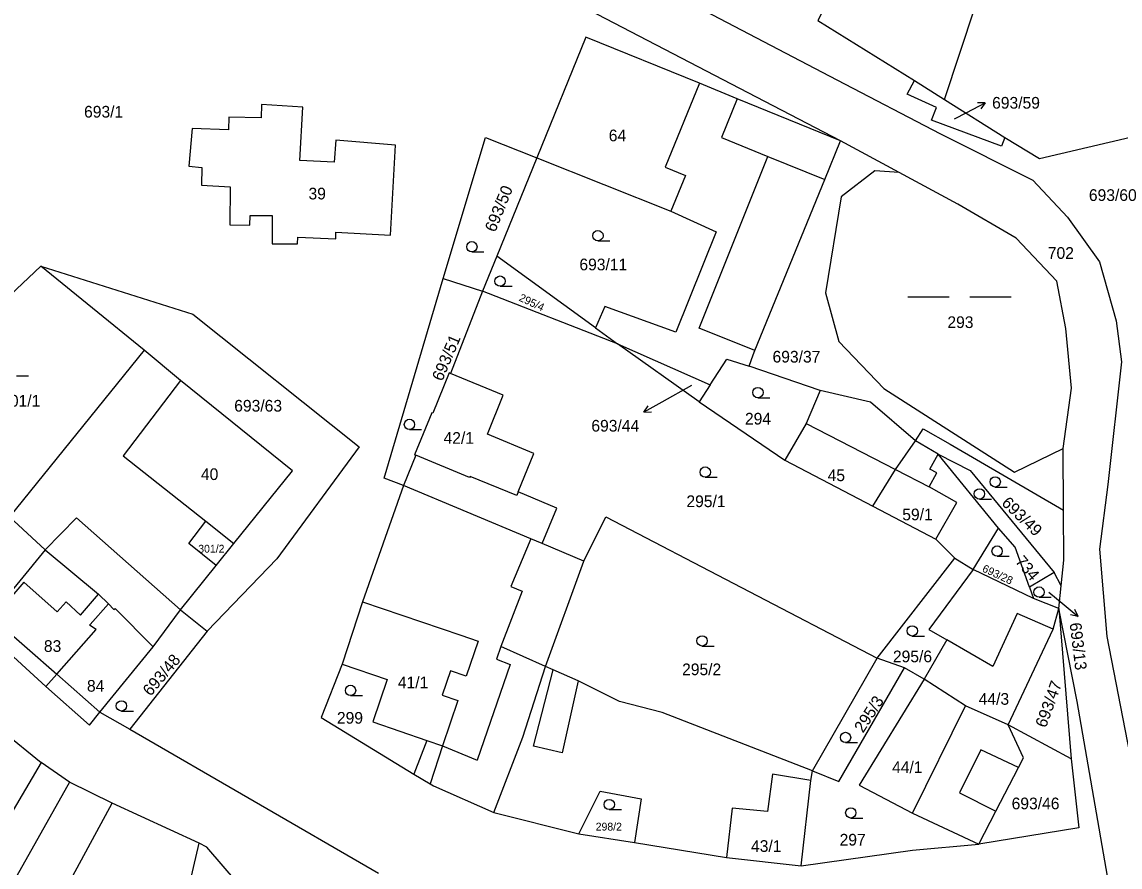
# Model space of a CAD drawing. Extents: x -7483133 to -743169, y -11317770 to -1127091.
# Drawn here: x -746401 to -746241.3, y -1132211.8 to -1132088.9 of the extents above; entities that cross this region are included whole.
import ezdxf

# ---------------------------------------------------------------- set-up
doc = ezdxf.new("R2010")
doc.units = 0
for name, color, linetype in [('Hranice parcel', 7, 'Continuous'), ('Parcelní čísla', 7, 'Continuous'), ('Pop  PČ popisy', 7, 'Continuous'), ('Vnitřní kresba', 7, 'Continuous'), ('Značky kultur', 7, 'Continuous')]:
    doc.layers.add(name, color=color, linetype=linetype)

msp = doc.modelspace()

# ---------------------------------------------------------------- linework, layer by layer
at = {"layer": 'Hranice parcel'}
for p, q in [((-746271.22, -1132097.41), (-746266.88, -1132100.2)), ((-746266.88, -1132100.2), (-746258.07, -1132105.71)), ((-746273.47, -1132110.79), (-746281.98, -1132106.18)), ((-746326.13, -1132108.66), (-746331.96, -1132122.97)), ((-746326.13, -1132108.66), (-746306.63, -1132116.44)), ((-746331.96, -1132122.97), (-746334.03, -1132128.06)), ((-746317.6, -1132133.4), (-746331.96, -1132122.97)), ((-746398.24, -1132124.43), (-746402.67, -1132128.64)), ((-746383.2, -1132136.66), (-746398.24, -1132124.43)), ((-746398.24, -1132124.43), (-746376.13, -1132131.39)), ((-746339.72, -1132126.2), (-746334.03, -1132128.06)), ((-746334.03, -1132128.06), (-746338.7, -1132140.02)), ((-746314.39, -1132135.73), (-746334.03, -1132128.06)), ((-746317.6, -1132133.4), (-746314.39, -1132135.73)), ((-746314.39, -1132135.73), (-746300.91, -1132141.67)), ((-746302.53, -1132144.17), (-746314.39, -1132135.73)), ((-746383.2, -1132136.66), (-746402.78, -1132160.86)), ((-746284.93, -1132142.52), (-746295.24, -1132138.98)), ((-746338.7, -1132140.02), (-746338.87, -1132139.95)), ((-746331.03, -1132143.2), (-746338.7, -1132140.02)), ((-746300.91, -1132141.67), (-746302.53, -1132144.17)), ((-746302.53, -1132144.17), (-746290.06, -1132152.64)), ((-746271.08, -1132149.84), (-746269.98, -1132148.07)), ((-746267.76, -1132151.76), (-746271.08, -1132149.84)), ((-746259.02, -1132162.52), (-746267.76, -1132151.76)), ((-746249.58, -1132159.89), (-746249.63, -1132150.94)), ((-746290.06, -1132152.64), (-746277.28, -1132159.31)), ((-746370.18, -1132164.75), (-746361.64, -1132154.17)), ((-746327.01, -1132164.06), (-746345.51, -1132156.33)), ((-746402.78, -1132160.86), (-746397.61, -1132165.68)), ((-746249.5, -1132167.15), (-746249.58, -1132159.89)), ((-746262.67, -1132168.54), (-746259.02, -1132162.52)), ((-746325.35, -1132164.75), (-746327.01, -1132164.06)), ((-746397.61, -1132165.68), (-746406.86, -1132176.98)), ((-746397.61, -1132165.68), (-746389.84, -1132172.12)), ((-746372.76, -1132167.96), (-746370.18, -1132164.75)), ((-746319.28, -1132167.34), (-746325.35, -1132164.75)), ((-746324.85, -1132182.62), (-746319.28, -1132167.34)), ((-746276.66, -1132181.4), (-746265.37, -1132166.88)), ((-746265.37, -1132166.88), (-746262.67, -1132168.54)), ((-746249.91, -1132170.92), (-746249.5, -1132167.15)), ((-746377.93, -1132174.38), (-746372.76, -1132167.96)), ((-746262.67, -1132168.54), (-746269.15, -1132177.26)), ((-746253.91, -1132172.73), (-746262.67, -1132168.54)), ((-746250.91, -1132168.99), (-746254.52, -1132171.09)), ((-746249.91, -1132170.92), (-746250.91, -1132168.99)), ((-746250.26, -1132174.19), (-746249.91, -1132170.92)), ((-746389.84, -1132172.12), (-746388.41, -1132173.53)), ((-746254.52, -1132171.09), (-746253.91, -1132172.73)), ((-746250.26, -1132174.19), (-746253.91, -1132172.73)), ((-746381.9, -1132179.76), (-746377.93, -1132174.38)), ((-746377.93, -1132174.38), (-746374.04, -1132177.52)), ((-746251.07, -1132177.2), (-746250.26, -1132174.19)), ((-746250.26, -1132174.19), (-746248.47, -1132196.06)), ((-746406.86, -1132176.98), (-746397.51, -1132185.52)), ((-746257.62, -1132191.11), (-746251.07, -1132177.2)), ((-746374.04, -1132177.52), (-746385.31, -1132191.74)), ((-746389.67, -1132189.29), (-746381.9, -1132179.76)), ((-746286.03, -1132197.8), (-746276.66, -1132181.4)), ((-746272.66, -1132182.81), (-746276.66, -1132181.4)), ((-746269.83, -1132184.49), (-746272.66, -1132182.81)), ((-746397.51, -1132185.52), (-746395.9, -1132183.77)), ((-746389.67, -1132189.29), (-746385.31, -1132191.74)), ((-746248.47, -1132196.06), (-746257.62, -1132191.11)), ((-746403.66, -1132192.14), (-746398.19, -1132196.61)), ((-746385.31, -1132191.74), (-746349.14, -1132212.69)), ((-746342.14, -1132193.39), (-746344.02, -1132198.28)), ((-746398.19, -1132196.61), (-746414.98, -1132225.06)), ((-746394.06, -1132199.47), (-746398.19, -1132196.61)), ((-746394.06, -1132199.47), (-746409.61, -1132226.97)), ((-746387.86, -1132202.51), (-746394.06, -1132199.47)), ((-746341.17, -1132199.97), (-746332.36, -1132203.87)), ((-746402.53, -1132229.49), (-746387.86, -1132202.51)), ((-746375.2, -1132208.32), (-746387.86, -1132202.51)), ((-746332.36, -1132203.87), (-746320.04, -1132206.95)), ((-746320.04, -1132206.95), (-746311.91, -1132208.23))]:
    msp.add_line(p, q, dxfattribs=at)
for points in [[(-746266.88, -1132100.2), (-746262.42, -1132086.72), (-746242.88, -1132045.31)], [(-746281.98, -1132106.18), (-746317.29, -1132087.85), (-746364.32, -1132063.67)], [(-746324.12, -1132075.54), (-746282.49, -1132097.32), (-746267.43, -1132105.17), (-746254.03, -1132111.91), (-746248.97, -1132117.3)], [(-746282.45, -1132083.18), (-746285.29, -1132088.71), (-746271.22, -1132097.41)], [(-746258.07, -1132105.71), (-746253.04, -1132108.76), (-746235.88, -1132104.76), (-746228.31, -1132088.24)], [(-746281.98, -1132106.18), (-746296.99, -1132100.07), (-746302.49, -1132097.83), (-746318.98, -1132091.11), (-746326.13, -1132108.66)], [(-746258.07, -1132105.71), (-746258.56, -1132106.96), (-746268.77, -1132103.18), (-746268.04, -1132101.35), (-746272.31, -1132099.42), (-746271.22, -1132097.41)], [(-746355.36, -1132120.45), (-746355.33, -1132119.49), (-746347.42, -1132119.91), (-746346.68, -1132106.82), (-746355.36, -1132106.11), (-746355.58, -1132109.28), (-746360.59, -1132109.08), (-746360.16, -1132101.31), (-746366.14, -1132100.93), (-746366.2, -1132102.85), (-746370.91, -1132102.78), (-746370.97, -1132104.58), (-746376.22, -1132104.42), (-746376.7, -1132109.89), (-746374.83, -1132110.1), (-746374.9, -1132112.66), (-746370.69, -1132112.9), (-746370.75, -1132118.4), (-746367.87, -1132118.47), (-746367.81, -1132117.06), (-746364.58, -1132117.06), (-746364.61, -1132121.16), (-746360.9, -1132121.16), (-746360.86, -1132120.23), (-746355.36, -1132120.45)], [(-746339.72, -1132126.2), (-746333.57, -1132105.7), (-746326.13, -1132108.66)], [(-746295.24, -1132138.98), (-746294.66, -1132137.31), (-746294.42, -1132136.7), (-746284.28, -1132111.82), (-746281.98, -1132106.18)], [(-746273.47, -1132110.79), (-746277.01, -1132110.58), (-746281.86, -1132114.35), (-746284.17, -1132128.28), (-746282.24, -1132135.36), (-746275.7, -1132142.21), (-746256.69, -1132154.37), (-746249.63, -1132150.94)], [(-746249.63, -1132150.94), (-746248.4, -1132142.18), (-746249.24, -1132133.5), (-746250.55, -1132126.59), (-746256.46, -1132120.37), (-746264.93, -1132115.42), (-746273.47, -1132110.79)], [(-746306.63, -1132116.44), (-746300.07, -1132119.44), (-746305.92, -1132134.02), (-746316.23, -1132130.3), (-746317.6, -1132133.4)], [(-746248.97, -1132117.3), (-746244.31, -1132123.79), (-746241.88, -1132132.35), (-746241.11, -1132138.34), (-746243.12, -1132156.17), (-746244.31, -1132165.56), (-746243.27, -1132178.27), (-746239.96, -1132195.24)], [(-746345.51, -1132156.33), (-746348.32, -1132155.23), (-746339.72, -1132126.2)], [(-746376.13, -1132131.39), (-746351.94, -1132150.67), (-746363.92, -1132166.96), (-746374.04, -1132177.52)], [(-746361.64, -1132154.17), (-746377.92, -1132141.05), (-746383.2, -1132136.66)], [(-746300.91, -1132141.67), (-746298.49, -1132137.94), (-746295.24, -1132138.98)], [(-746338.87, -1132139.95), (-746341.27, -1132145.79), (-746341.4, -1132145.74), (-746343.89, -1132151.87), (-746343.74, -1132151.93), (-746345.51, -1132156.33)], [(-746326.54, -1132151.64), (-746333.32, -1132148.85), (-746331.03, -1132143.2)], [(-746284.93, -1132142.52), (-746286.99, -1132147.28), (-746290.06, -1132152.64)], [(-746271.08, -1132149.84), (-746277.62, -1132144.21), (-746284.93, -1132142.52)], [(-746269.98, -1132148.07), (-746266.05, -1132150.32), (-746249.58, -1132159.89)], [(-746277.28, -1132159.31), (-746273.97, -1132154.01), (-746271.08, -1132149.84)], [(-746325.35, -1132164.75), (-746323.2, -1132159.6), (-746328.82, -1132157.26), (-746326.54, -1132151.64)], [(-746267.76, -1132151.76), (-746263.14, -1132154.13), (-746250.91, -1132168.99)], [(-746345.51, -1132156.33), (-746351.46, -1132173.24), (-746354.43, -1132182.28)], [(-746277.28, -1132159.31), (-746268.1, -1132164.11), (-746265.37, -1132166.88)], [(-746319.28, -1132167.34), (-746316.09, -1132160.88), (-746276.66, -1132181.4)], [(-746372.76, -1132167.96), (-746376.72, -1132164.77), (-746374.25, -1132161.52), (-746370.18, -1132164.75)], [(-746254.52, -1132171.09), (-746256.61, -1132165.3), (-746259.02, -1132162.52)], [(-746395.9, -1132183.77), (-746390.21, -1132177.25), (-746391.15, -1132176.62), (-746391.07, -1132176.53), (-746388.41, -1132173.53)], [(-746388.41, -1132173.53), (-746387.63, -1132174.36), (-746387.45, -1132174.22), (-746381.9, -1132179.76)], [(-746239.72, -1132225.13), (-746242.13, -1132218.98), (-746247.56, -1132187.7), (-746250.26, -1132174.19)], [(-746269.15, -1132177.26), (-746266.52, -1132178.78), (-746269.83, -1132184.49)], [(-746354.43, -1132182.28), (-746357.46, -1132190.03), (-746344.02, -1132198.28)], [(-746354.43, -1132182.28), (-746347.89, -1132184.52), (-746349.97, -1132190.7), (-746342.14, -1132193.39)], [(-746332.36, -1132203.87), (-746328.16, -1132192.93), (-746324.85, -1132182.62)], [(-746286.03, -1132197.8), (-746307.91, -1132189.33), (-746314.12, -1132187.7), (-746320.12, -1132184.74), (-746323.77, -1132183.11), (-746324.85, -1132182.62)], [(-746286.03, -1132197.8), (-746282.24, -1132199.36), (-746272.66, -1132182.81)], [(-746269.83, -1132184.49), (-746279.28, -1132199.88), (-746271.52, -1132203.95), (-746261.88, -1132208.46)], [(-746257.62, -1132191.11), (-746263.83, -1132188.34), (-746269.83, -1132184.49)], [(-746397.51, -1132185.52), (-746391.16, -1132191.17), (-746389.67, -1132189.29)], [(-746261.88, -1132208.46), (-746259.4, -1132203.66), (-746256.11, -1132197.3), (-746255.38, -1132195.9), (-746257.62, -1132191.11)], [(-746248.47, -1132196.06), (-746247.35, -1132206.07), (-746261.88, -1132208.46)], [(-746287.72, -1132211.62), (-746286.31, -1132199.21), (-746286.03, -1132197.8)], [(-746344.02, -1132198.28), (-746341.62, -1132199.71), (-746341.17, -1132199.97)], [(-746320.04, -1132206.95), (-746316.94, -1132200.77), (-746310.94, -1132201.9), (-746311.91, -1132208.23)], [(-746383.65, -1132246.38), (-746379.95, -1132228.73), (-746375.2, -1132208.32)], [(-746361.01, -1132224.1), (-746374.1, -1132208.89), (-746375.2, -1132208.32)], [(-746311.91, -1132208.23), (-746298.54, -1132210.41), (-746287.72, -1132211.62)], [(-746287.72, -1132211.62), (-746271.53, -1132209.32), (-746261.88, -1132208.46)]]:
    msp.add_lwpolyline(points, dxfattribs=at)
at = {"layer": 'Pop  PČ popisy'}
for p, q in [((-746263.59, -1132102.07), (-746260.94, -1132100.66)), ((-746260.94, -1132100.66), (-746262.06, -1132100.69)), ((-746260.94, -1132100.66), (-746261.59, -1132101.57)), ((-746265.39, -1132103.02), (-746263.59, -1132102.07)), ((-746303.64, -1132141.76), (-746307.97, -1132144.18)), ((-746307.97, -1132144.18), (-746310.59, -1132145.64)), ((-746310.59, -1132145.64), (-746309.96, -1132144.71)), ((-746310.59, -1132145.64), (-746309.48, -1132145.59)), ((-746251.69, -1132171.81), (-746249.74, -1132173.44)), ((-746249.74, -1132173.44), (-746247.44, -1132175.37)), ((-746247.44, -1132175.37), (-746248.53, -1132175.11)), ((-746247.44, -1132175.37), (-746247.89, -1132174.34))]:
    msp.add_line(p, q, dxfattribs=at)
at = {"layer": 'Vnitřní kresba'}
for p, q in [((-746302.49, -1132097.83), (-746307.46, -1132110.02)), ((-746296.99, -1132100.07), (-746299.29, -1132105.7)), ((-746299.29, -1132105.7), (-746292.53, -1132108.46)), ((-746302.51, -1132133.44), (-746292.53, -1132108.46)), ((-746292.53, -1132108.46), (-746284.28, -1132111.82)), ((-746307.46, -1132110.02), (-746304.5, -1132111.22)), ((-746304.5, -1132111.22), (-746306.63, -1132116.44)), ((-746294.42, -1132136.7), (-746302.51, -1132133.44)), ((-746377.92, -1132141.05), (-746386.25, -1132151.99)), ((-746286.99, -1132147.28), (-746273.97, -1132154.01)), ((-746269.01, -1132153.93), (-746267.76, -1132151.76)), ((-746386.25, -1132151.99), (-746374.25, -1132161.52)), ((-746335.91, -1132155.17), (-746343.74, -1132151.93)), ((-746273.97, -1132154.01), (-746269.1, -1132156.5)), ((-746269.1, -1132156.5), (-746267.99, -1132154.49)), ((-746267.99, -1132154.49), (-746269.01, -1132153.93)), ((-746335.83, -1132154.99), (-746335.91, -1132155.17)), ((-746329.03, -1132157.78), (-746335.83, -1132154.99)), ((-746265.06, -1132158.79), (-746269.1, -1132156.5)), ((-746328.82, -1132157.26), (-746329.03, -1132157.78)), ((-746268.1, -1132164.11), (-746265.06, -1132158.79)), ((-746393.06, -1132161.01), (-746397.61, -1132165.68)), ((-746377.93, -1132174.38), (-746393.06, -1132161.01)), ((-746327.01, -1132164.06), (-746329.9, -1132170.98)), ((-746400.72, -1132170.37), (-746405.23, -1132175.59)), ((-746395.85, -1132174.69), (-746400.72, -1132170.37)), ((-746392.49, -1132175.17), (-746389.84, -1132172.12)), ((-746328.24, -1132171.67), (-746331.34, -1132179.73)), ((-746329.9, -1132170.98), (-746328.24, -1132171.67)), ((-746394.53, -1132173.23), (-746395.85, -1132174.69)), ((-746392.49, -1132175.17), (-746394.53, -1132173.23)), ((-746351.46, -1132173.24), (-746337.16, -1132178.1)), ((-746405.23, -1132175.59), (-746395.9, -1132183.77)), ((-746256.3, -1132174.95), (-746259.81, -1132182.62)), ((-746251.07, -1132177.2), (-746256.3, -1132174.95)), ((-746337.16, -1132178.1), (-746334.67, -1132178.95)), ((-746259.81, -1132182.62), (-746266.52, -1132178.78)), ((-746334.67, -1132178.95), (-746336.41, -1132184.06)), ((-746331.34, -1132179.73), (-746331.97, -1132181.56)), ((-746324.85, -1132182.62), (-746331.34, -1132179.73)), ((-746331.97, -1132181.56), (-746330, -1132182.34)), ((-746338.7, -1132183.28), (-746339.9, -1132186.81)), ((-746336.41, -1132184.06), (-746338.7, -1132183.28)), ((-746330, -1132182.34), (-746334.82, -1132196.26)), ((-746326.61, -1132194.2), (-746323.77, -1132183.11)), ((-746395.9, -1132183.77), (-746389.67, -1132189.29)), ((-746320.12, -1132184.74), (-746322.45, -1132195.19)), ((-746339.9, -1132186.81), (-746337.61, -1132187.59)), ((-746337.61, -1132187.59), (-746339.85, -1132194.17)), ((-746271.52, -1132203.95), (-746263.83, -1132188.34)), ((-746342.14, -1132193.39), (-746339.85, -1132194.17)), ((-746339.85, -1132194.17), (-746341.62, -1132199.71)), ((-746339.85, -1132194.17), (-746334.82, -1132196.26)), ((-746322.45, -1132195.19), (-746326.61, -1132194.2)), ((-746261.59, -1132194.74), (-746264.68, -1132201.02)), ((-746256.11, -1132197.3), (-746261.59, -1132194.74)), ((-746291.88, -1132198.29), (-746292.59, -1132203.73)), ((-746286.31, -1132199.21), (-746291.88, -1132198.29)), ((-746264.68, -1132201.02), (-746259.4, -1132203.66)), ((-746297.74, -1132203.24), (-746298.54, -1132210.41)), ((-746292.59, -1132203.73), (-746297.74, -1132203.24))]:
    msp.add_line(p, q, dxfattribs=at)
at = {"layer": 'Značky kultur'}
for p, q in [((-746317.24, -1132120.74), (-746315.49, -1132120.74)), ((-746335.57, -1132122.35), (-746333.82, -1132122.35)), ((-746331.48, -1132127.35), (-746329.73, -1132127.35)), ((-746272.19, -1132128.9), (-746266.19, -1132128.9)), ((-746263.19, -1132128.9), (-746257.19, -1132128.9)), ((-746401.78, -1132140.35), (-746400.03, -1132140.35)), ((-746293.98, -1132143.56), (-746292.23, -1132143.56)), ((-746344.64, -1132148.18), (-746342.89, -1132148.18)), ((-746301.64, -1132155.11), (-746299.89, -1132155.11)), ((-746259.49, -1132156.54), (-746257.74, -1132156.54)), ((-746261.79, -1132158.29), (-746260.04, -1132158.29)), ((-746259.21, -1132166.6), (-746257.46, -1132166.6)), ((-746253.12, -1132172.56), (-746251.37, -1132172.56)), ((-746271.54, -1132178.21), (-746269.79, -1132178.21)), ((-746302.11, -1132179.66), (-746300.36, -1132179.66)), ((-746353.21, -1132186.86), (-746351.46, -1132186.86)), ((-746386.52, -1132189.11), (-746384.77, -1132189.11)), ((-746281.25, -1132193.7), (-746279.5, -1132193.7)), ((-746315.59, -1132203.45), (-746313.84, -1132203.45)), ((-746280.48, -1132204.67), (-746278.73, -1132204.67))]:
    msp.add_line(p, q, dxfattribs=at)
for centre in [(-746317.24, -1132119.99), (-746335.57, -1132121.6), (-746331.48, -1132126.6), (-746293.98, -1132142.81), (-746344.64, -1132147.43), (-746301.64, -1132154.36), (-746259.49, -1132155.79), (-746261.79, -1132157.54), (-746259.21, -1132165.85), (-746253.12, -1132171.81), (-746271.54, -1132177.46), (-746302.11, -1132178.91), (-746353.21, -1132186.11), (-746386.52, -1132188.36), (-746281.25, -1132192.95), (-746315.59, -1132202.7), (-746280.48, -1132203.92)]:
    msp.add_circle(centre, 0.75, dxfattribs=at)

# ---------------------------------------------------------------- texts
at = {"layer": 'Parcelní čísla'}
for s, height, p in [('693/59', 1.7, (-746259.94, -1132101.52)), ('693/1', 1.7, (-746391.95, -1132102.82)), ('64', 1.7, (-746315.67, -1132106.27)), ('39', 1.7, (-746359.32, -1132114.72)), ('693/60', 1.7, (-746245.87, -1132114.94)), ('702', 1.7, (-746251.84, -1132123.36)), ('693/11', 1.7, (-746319.94, -1132125.03)), ('293', 1.7, (-746266.44, -1132133.42)), ('693/37', 1.7, (-746291.86, -1132138.44)), ('301/1', 1.7, (-746404, -1132144.85)), ('693/63', 1.7, (-746370.12, -1132145.57)), ('693/44', 1.7, (-746318.2, -1132148.48)), ('294', 1.7, (-746295.87, -1132147.45)), ('42/1', 1.7, (-746339.69, -1132150.25)), ('40', 1.7, (-746374.96, -1132155.52)), ('45', 1.7, (-746283.85, -1132155.68)), ('295/1', 1.7, (-746304.38, -1132159.46)), ('59/1', 1.7, (-746273, -1132161.38)), ('301/2', 1.139, (-746375.35, -1132166.08)), ('83', 1.7, (-746397.79, -1132180.51)), ('295/6', 1.7, (-746274.36, -1132182.02)), ('295/2', 1.7, (-746305.01, -1132183.9)), ('84', 1.7, (-746391.53, -1132186.3)), ('41/1', 1.7, (-746346.33, -1132185.8)), ('44/3', 1.7, (-746261.89, -1132188.2)), ('299', 1.7, (-746355.19, -1132190.95)), ('44/1', 1.7, (-746274.48, -1132198.13)), ('693/46', 1.7, (-746257.1, -1132203.4)), ('298/2', 1.14, (-746317.57, -1132206.49)), ('297', 1.7, (-746282.11, -1132208.67)), ('43/1', 1.7, (-746294.99, -1132209.59))]:
    msp.add_text(s, height=height, dxfattribs=at).set_placement(p)
for s, height, rotation, p in [('693/50', 1.7, 68, (-746332.18, -1132119.59)), ('295/4', 1.14, 335, (-746328.83, -1132129.4)), ('693/51', 1.7, 67, (-746339.88, -1132141.26)), ('693/49', 1.7, 316, (-746258.68, -1132159)), ('734', 1.7, 310, (-746256.67, -1132167.41)), ('693/28', 1.14, 335, (-746261.48, -1132168.78)), ('693/13', 1.7, 277, (-746248.68, -1132176.35)), ('693/48', 1.7, 50, (-746382.28, -1132187.05)), ('693/47', 1.7, 70, (-746252.12, -1132191.65)), ('295/3', 1.7, 57, (-746278.7, -1132192.39))]:
    msp.add_text(s, height=height, rotation=rotation, dxfattribs=at).set_placement(p)

doc.saveas('drawing.dxf')
